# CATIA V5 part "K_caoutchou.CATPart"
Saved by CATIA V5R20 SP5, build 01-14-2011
Part number: caoutchou
Bounding box of the stored display mesh (mm): x 0 to 48.5, y -36 to 36, z -35.99 to 35.99
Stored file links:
  G:\Khaled_CFAO_2011\ST2M\ST2M_GR1\lpierredon\Khaled\CAD_thinkMOTION\K_caoutchou.CATPart
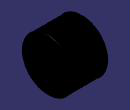
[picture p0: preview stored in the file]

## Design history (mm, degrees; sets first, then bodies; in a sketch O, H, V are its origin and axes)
Body1 (main body)
  Sketch1 on yz-plane, origin (0, 0, 0), H (0, 1, 0), V (0, 0, 1)
    circle A1 centre (0, 0) radius 30
    circle A2 centre (0, 0) radius 36
    distance A1 A2 = 6
    radius A1 = 30
  Pad1: profile Sketch1, direction (1, 0, 0), length 48.5
  Fillet1: radius 1, on edge [face of Pad1 from Sketch1.A2 | end face of Pad1]; face of Pad1 from Sketch1.A2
